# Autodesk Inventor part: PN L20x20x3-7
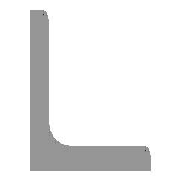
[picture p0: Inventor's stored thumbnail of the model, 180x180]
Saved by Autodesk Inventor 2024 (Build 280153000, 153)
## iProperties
Company: ATC
_CCFamilyMember: 10
_CCFamilyDisplayName: PN EN 10056-1 (Kątownik równoramienny) - Kątownik równoramienny
_FrameMemberDoc: Frame Member File
_Version: 15.0.0
Created: 2023-03
Part Number: PN L20x20x3-7
Material: Ogólny
Description: Kątownik równoramienny
Document SubType Name: Modeling
Standard: PN EN 10056-1
Designer: Andrzej Jaskulski
Standards Organization: PN
Language: pl-PL
Size Designation: L20x20x3
Categories: <MemberInstance><Categories><Category DisplayName="Kształtowniki konstrukcyjne" InternalName="089c4875-fa83-4c05-b084-43b9cc11f5ed" Mnemonic="GRDR"><CategoryPar
Stock Number: L20x20x3
Density: 1 g/cm^3
Appearance: Domyślna
Checked By: A.J.
Engr Approved By: Andrzej Jaskulski
Mfg Approved By: Andrzej Jaskulski
Authority: A.J.
G_L: 294,082 mm
G_W: 20,000 mm
G_H: 20,000 mm
+8060BEBE-1D60-48CA-8EF9-F1276D2108D7+CUTDETAIL1: Kąt cięcia 53,65 deg
+81A88140-A87E-48C4-98E8-5C64B54995CD+CUTDETAIL2: Kąt cięcia 53,65 deg
IsCustomPart: 1
Author: Andrzej Jaskulski
Title: A.J.: Kurs R2024-MEP
Revision Number: 1/24
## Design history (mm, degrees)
node "Płaszczyzna początkowa"
node "Płaszczyzna końcowa"
sketch "Szkic"
  geometry: L1 (-2.975, 0.525)-(-2.975, 12.275); L2 (-5.975, 14.025)-(-4.725, 14.025); L3 (-5.975, -5.975)-(-5.975, 14.025); L4 (-5.975, -5.975)-(14.025, -5.975); L5 (14.025, -4.725)-(14.025, -5.975); L6 (0.525, -2.975)-(12.275, -2.975); L7 (0, 18.46)-(0, -10.048) reference; L8 (-10.048, 0)-(18.46, 0) reference; A1 r 3.5 centre (0.525, 0.525) between (-2.975, 0.525) and (0.525, -2.975); A2 r 1.75 centre (-4.725, 12.275) between (-2.975, 12.275) and (-4.725, 14.025); A3 r 1.75 centre (12.275, -4.725) between (14.025, -4.725) and (12.275, -2.975); 3 further points
  constraints: 12 end point, 6 point on circle, 6 point on line, 6 tangent, 3 centre point, 3 horizontal, 3 vertical, 1 equal radius
  dimensions: "d4" = 20 distance of L3.start L4.end (= b); "d6" = 20 distance of L3.start L2.start (= b); "d8" = 3 distance of point (14.025, -2.975) L4.end (= ParT); "d10" = 3 distance of L2.start point (-2.975, 14.025) (= ParT); "d17" = 3.5 radius of A1 (= R); "d18" = 1.75 radius of A2 (= R1); "d19" = 5.97509 distance between parallel lines of L8 L4 (= ex); "d20" = 5.97509 distance between parallel lines of L3 L7 (= d19)
extrude "Bryła" new body sketch "Szkic" stored distance "d11" = 294.08233 (= G_L); taper "d12" = 0 deg
node "Driven Length"
  sketch "Sketch3"
    geometry: L1 (0, 0)-(10, 0) reference
    constraints: 2 end point, 1 horizontal
  workplane "Work Plane10"
node "Płaszczyzna konstrukcyjna11"
feature "Podział1"
node "Płaszczyzna konstrukcyjna12"
feature "Podział2"
body "Solid1"
sketch "Sketch4"
  geometry: L1 (-2, 0)-(12, 0) reference; L2 (-2, 294.082)-(12, 294.082) reference
  dimensions: "d24" = 294.08233 distance between parallel lines of L1 L2 (derived)
other parameters: "b" = 20 [user parameter; used in 3 equation terms], "ParT" = 3 [user parameter; used in 3 equation terms], "R" = 3.5 [user parameter; used in 1 equation term], "R1" = 1.75 [user parameter; used in 1 equation term], "G_L" = 294.08233 (= d24) [user parameter; used in 1 equation term], "d7" = 4 (derived), "d9" = 4 (derived), "ex" = 5.97509 (computed from b, ParT) [user parameter; used in 1 equation term], "G_OFFSET_START" = 0 [user parameter; used in 1 equation term], "G_OFFSET_END" = 14.70198 [user parameter; used in 1 equation term], "d21" = 0 (computed from G_OFFSET_START), "d22" = 294.08233 (= G_OFFSET_END + B_L), "B_L" = 279.38035 [user parameter; used in 1 equation term], "d23" = 90 deg
